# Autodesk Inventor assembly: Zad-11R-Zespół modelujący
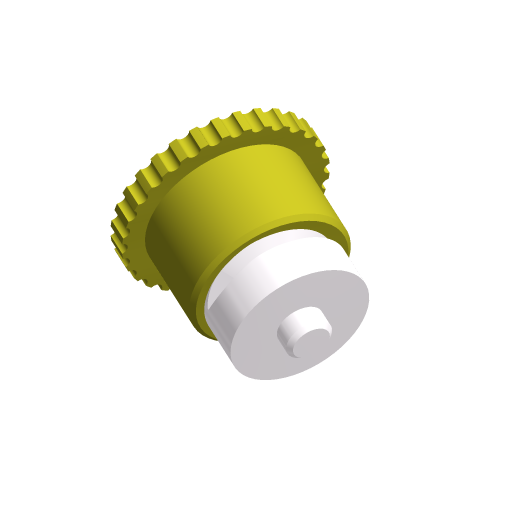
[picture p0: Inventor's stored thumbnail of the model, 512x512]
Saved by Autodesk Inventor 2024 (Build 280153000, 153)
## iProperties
Created: 2023-03
Part Number: Zad-11R-Zespół modelujący
Document SubType Name: Assembly
Designer: Andrzej Jaskulski
Checked By: A.J.
Engr Approved By: Andrzej Jaskulski
Mfg Approved By: Andrzej Jaskulski
Authority: A.J.
Company: ATC
Control State: 0
Master: False
Checked Out: False
Shininess: 20.0
Length Units: 11269
Angle Units: 11279
Time Units: 11290
Mass Units: 11283
Length Display Precision: 3
Angle Display Precision: 2
Compacted: True
Density: 0.0
Volumn: 0.0
Area: 0.0
PropertySet Name: Model Information
Title: A.J.: Kurs R2024-MEP
Author: Andrzej Jaskulski
Revision Number: 1/24
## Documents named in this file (3)
- C:\Users\AndJas\Documents\R2024-MEP\Obszar roboczy\Zad-11R-Zespół modelujący.iam
- C:\Users\AndJas\Documents\R2024-MEP\Obszar roboczy\Zad-10R.ipt
- C:\Users\AndJas\Documents\R2024-MEP\Obszar roboczy\Zad-11R-Surówka.ipt
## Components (2 placed, 2 different names)
1. Zad-11R-Surówka:1 — Wstawiające:1
2. Zad-10R:1 — Wstawiające:1
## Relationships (1: Insert 1)
- Wstawiające:1 [Insert]: Zad-11R-Surówka:1 ↔ Zad-10R:1
